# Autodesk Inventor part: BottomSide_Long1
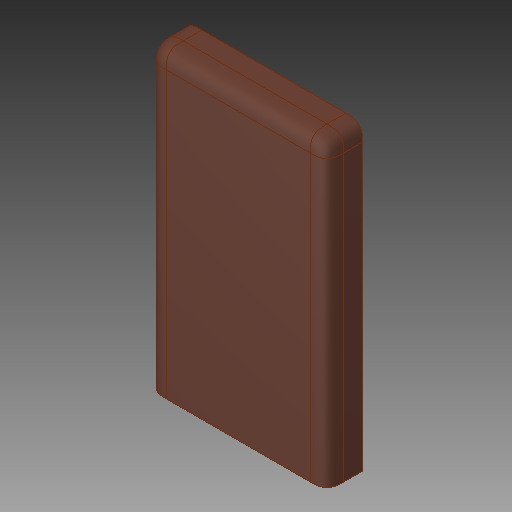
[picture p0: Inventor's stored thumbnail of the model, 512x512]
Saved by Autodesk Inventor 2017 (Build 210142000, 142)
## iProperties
Created: 2017-05
Part Number: BottomSide_Long1
Material: Generic
Document SubType Name: Modeling
Designer: Savy
Density: 1 g/cm^3
Appearance: Default
Mass: 83.8277 g
Surface Area: 184.817 cm^2
Volume: 83.8277 cm^3
Author: Savy
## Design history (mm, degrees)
feature "SOLID1"
body "Solid1"
